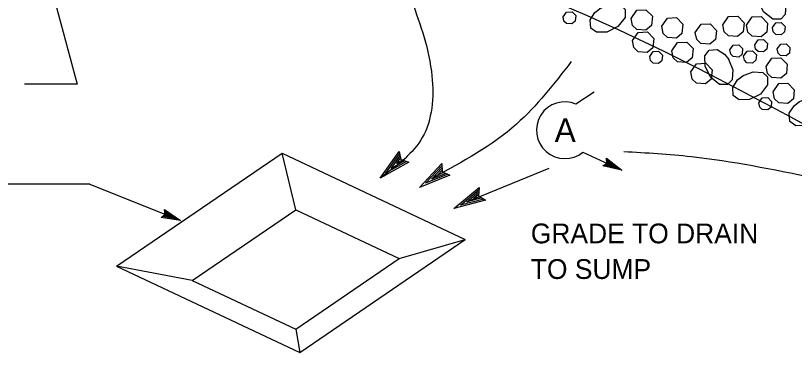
# Model space of a CAD drawing. Extents: x 6709491 to 6710959, y 1869789 to 1870763.
# Drawn here: x 6710515.2 to 6710751.9, y 1870221.6 to 1870323.8 of the extents above; entities that cross this region are included whole.
import ezdxf

# ---------------------------------------------------------------- set-up
doc = ezdxf.new("R2010")
doc.units = 0
for name, color, linetype in [('56 Stg 3 Anno', 7, 'Continuous'), ('57 Undefined', 7, 'Continuous'), ('60 Nongeo Data', 7, 'Continuous')]:
    doc.layers.add(name, color=color, linetype=linetype)

msp = doc.modelspace()

# ---------------------------------------------------------------- linework, layer by layer
at = {"layer": '56 Stg 3 Anno'}
for p, q in [((6710522.92, 1870344.3), (6710533.94, 1870302.96)), ((6710533.94, 1870302.96), (6710517.96, 1870302.96)), ((6710691.06, 1870300.55), (6710685.5, 1870296.97)), ((6710687.63, 1870282.38), (6710699.46, 1870276.93)), ((6710693.69, 1870278.18), (6710694.92, 1870279.02)), ((6710698.24, 1870277.49), (6710694.04, 1870278.4)), ((6710697.05, 1870278.04), (6710694.33, 1870278.63)), ((6710695.84, 1870278.6), (6710694.68, 1870278.85)), ((6710694.92, 1870279.02), (6710694.76, 1870280.51)), ((6710694.76, 1870280.51), (6710694.76, 1870280.51)), ((6710694.76, 1870280.51), (6710699.46, 1870276.93)), ((6710694.81, 1870280.11), (6710698.26, 1870277.49)), ((6710694.87, 1870279.71), (6710697.05, 1870278.04)), ((6710694.88, 1870279.33), (6710695.84, 1870278.6)), ((6710699.46, 1870276.93), (6710693.69, 1870278.18)), ((6710693.69, 1870278.18), (6710693.69, 1870278.18)), ((6710699.46, 1870276.93), (6710699.46, 1870276.93)), ((6710537.79, 1870272.64), (6710496.85, 1870272.64)), ((6710537.79, 1870272.64), (6710565.34, 1870261.62)), ((6710560.7, 1870263.47), (6710560.47, 1870264.95)), ((6710560.47, 1870264.95), (6710560.47, 1870264.95)), ((6710560.47, 1870264.95), (6710565.34, 1870261.62)), ((6710560.53, 1870264.56), (6710564.11, 1870262.11)), ((6710560.61, 1870264.15), (6710562.87, 1870262.6)), ((6710559.51, 1870262.57), (6710560.7, 1870263.47)), ((6710565.34, 1870261.62), (6710559.51, 1870262.57)), ((6710559.51, 1870262.57), (6710559.51, 1870262.57)), ((6710564.09, 1870262.11), (6710559.85, 1870262.81)), ((6710562.87, 1870262.6), (6710560.13, 1870263.05)), ((6710561.64, 1870263.1), (6710560.47, 1870263.29)), ((6710560.65, 1870263.78), (6710561.64, 1870263.1)), ((6710565.34, 1870261.62), (6710565.34, 1870261.62))]:
    msp.add_line(p, q, dxfattribs=at)
msp.add_arc((6710682.15, 1870289.04), 8.62, 67.1261, 309.4327, dxfattribs=at)
at = {"layer": '60 Nongeo Data'}
for p, q in [((6710545.91, 1870247.74), (6710596.21, 1870282.03)), ((6710596.21, 1870282.03), (6710651.87, 1870255.89)), ((6710600.37, 1870264.89), (6710596.21, 1870282.03)), ((6710626.02, 1870274.46), (6710631.78, 1870282.56)), ((6710627.69, 1870275.98), (6710631.89, 1870281.88)), ((6710629.34, 1870277.46), (6710632.05, 1870281.27)), ((6710631, 1870278.95), (6710632.16, 1870280.58)), ((6710631.78, 1870282.56), (6710631.78, 1870282.56)), ((6710631.78, 1870282.56), (6710632.26, 1870280.1)), ((6710634.68, 1870279.36), (6710626.02, 1870274.46)), ((6710634.03, 1870279.55), (6710627.68, 1870275.96)), ((6710633.36, 1870279.73), (6710629.34, 1870277.46)), ((6710632.77, 1870279.95), (6710631, 1870278.95)), ((6710632.26, 1870280.1), (6710634.68, 1870279.36)), ((6710634.68, 1870279.36), (6710634.68, 1870279.36)), ((6710637.96, 1870271.69), (6710644.74, 1870278.96)), ((6710639.81, 1870272.97), (6710644.76, 1870278.26)), ((6710644.74, 1870278.96), (6710644.74, 1870278.96)), ((6710644.74, 1870278.96), (6710644.89, 1870276.45)), ((6710641.64, 1870274.22), (6710644.84, 1870277.64)), ((6710645.93, 1870275.94), (6710641.64, 1870274.22)), ((6710643.49, 1870275.48), (6710644.85, 1870276.95)), ((6710645.38, 1870276.24), (6710643.49, 1870275.48)), ((6710644.89, 1870276.45), (6710647.18, 1870275.4)), ((6710677.28, 1870277.46), (6710652.25, 1870267.22)), ((6710626.02, 1870274.46), (6710626.02, 1870274.46)), ((6710647.18, 1870275.4), (6710637.96, 1870271.69)), ((6710646.57, 1870275.67), (6710639.8, 1870272.96)), ((6710647.18, 1870275.4), (6710647.18, 1870275.4)), ((6710637.96, 1870271.69), (6710637.96, 1870271.69)), ((6710648.41, 1870265.3), (6710656.08, 1870271.62)), ((6710656.08, 1870271.62), (6710655.91, 1870269.12)), ((6710656.08, 1870271.62), (6710656.08, 1870271.62)), ((6710650.42, 1870266.32), (6710656.01, 1870270.93)), ((6710652.4, 1870267.32), (6710656.01, 1870270.3)), ((6710654.39, 1870268.34), (6710655.93, 1870269.61)), ((6710656.36, 1870268.84), (6710654.39, 1870268.34)), ((6710655.91, 1870269.12), (6710658.04, 1870267.77)), ((6710658.04, 1870267.77), (6710648.41, 1870265.3)), ((6710657.47, 1870268.13), (6710650.4, 1870266.31)), ((6710656.87, 1870268.47), (6710652.4, 1870267.32)), ((6710658.04, 1870267.77), (6710658.04, 1870267.77)), ((6710568.89, 1870243.43), (6710600.37, 1870264.89)), ((6710600.37, 1870264.89), (6710631.82, 1870250.12)), ((6710648.41, 1870265.3), (6710648.41, 1870265.3)), ((6710601.56, 1870221.61), (6710651.87, 1870255.89)), ((6710631.82, 1870250.12), (6710651.87, 1870255.89)), ((6710600.34, 1870228.66), (6710631.82, 1870250.12)), ((6710545.91, 1870247.74), (6710601.56, 1870221.61)), ((6710568.89, 1870243.43), (6710545.91, 1870247.74)), ((6710568.89, 1870243.43), (6710600.34, 1870228.66)), ((6710600.34, 1870228.66), (6710601.56, 1870221.61))]:
    msp.add_line(p, q, dxfattribs=at)
for points in [[(6710748.03, 1870330.39), (6710749.32, 1870327.14), (6710749.06, 1870324.15), (6710747.71, 1870322.73), (6710745.28, 1870322.77), (6710742.53, 1870324.93), (6710740.86, 1870328.26), (6710740.81, 1870331.4), (6710742.06, 1870333.17), (6710744.56, 1870333.34), (6710746.8, 1870331.9), (6710748.11, 1870330.26)], [(6710692.79, 1870325.96), (6710696.05, 1870327.25), (6710699.03, 1870327), (6710700.46, 1870325.64), (6710700.41, 1870323.22), (6710698.25, 1870320.46), (6710694.92, 1870318.8), (6710691.78, 1870318.74), (6710690.01, 1870320), (6710689.85, 1870322.5), (6710691.28, 1870324.74), (6710692.92, 1870326.05)], [(6710702.26, 1870322.96), (6710704, 1870325.43), (6710706.77, 1870325.59), (6710708.71, 1870323.59), (6710708.43, 1870320.78), (6710706.71, 1870319.36), (6710703.97, 1870319.56), (6710702.68, 1870320.81), (6710702.26, 1870322.96)], [(6710681.59, 1870323.42), (6710682.63, 1870324.9), (6710684.3, 1870325), (6710685.46, 1870323.8), (6710685.29, 1870322.11), (6710684.26, 1870321.26), (6710682.61, 1870321.38), (6710681.84, 1870322.13), (6710681.59, 1870323.42)], [(6710711.56, 1870320.56), (6710713.29, 1870323.03), (6710716.07, 1870323.19), (6710718, 1870321.19), (6710717.72, 1870318.39), (6710716.01, 1870316.96), (6710713.27, 1870317.16), (6710711.98, 1870318.41), (6710711.56, 1870320.56)], [(6710730.12, 1870321.02), (6710731.86, 1870323.5), (6710734.64, 1870323.66), (6710736.57, 1870321.65), (6710736.29, 1870318.85), (6710734.57, 1870317.42), (6710731.83, 1870317.62), (6710730.54, 1870318.87), (6710730.12, 1870321.02)], [(6710737.28, 1870320.92), (6710739.02, 1870323.39), (6710741.79, 1870323.55), (6710743.73, 1870321.55), (6710743.45, 1870318.74), (6710741.73, 1870317.32), (6710738.99, 1870317.52), (6710737.7, 1870318.77), (6710737.28, 1870320.92)], [(6710721.77, 1870318.7), (6710723.51, 1870321.18), (6710726.28, 1870321.33), (6710728.21, 1870319.33), (6710727.93, 1870316.53), (6710726.22, 1870315.1), (6710723.48, 1870315.3), (6710722.19, 1870316.55), (6710721.77, 1870318.7)], [(6710745.19, 1870320.15), (6710746.24, 1870321.64), (6710747.9, 1870321.73), (6710749.06, 1870320.53), (6710748.89, 1870318.85), (6710747.86, 1870317.99), (6710746.22, 1870318.11), (6710745.44, 1870318.86), (6710745.19, 1870320.15)], [(6710702.69, 1870316.24), (6710704.43, 1870318.71), (6710707.21, 1870318.87), (6710709.14, 1870316.87), (6710708.86, 1870314.06), (6710707.15, 1870312.64), (6710704.41, 1870312.84), (6710703.11, 1870314.09), (6710702.7, 1870316.24)], [(6710739.81, 1870314.93), (6710740.85, 1870316.42), (6710742.52, 1870316.51), (6710743.68, 1870315.31), (6710743.51, 1870313.63), (6710742.48, 1870312.77), (6710740.83, 1870312.89), (6710740.06, 1870313.64), (6710739.81, 1870314.93)], [(6710714.65, 1870313.15), (6710716.39, 1870315.63), (6710719.16, 1870315.78), (6710721.09, 1870313.78), (6710720.82, 1870310.98), (6710719.1, 1870309.55), (6710716.36, 1870309.75), (6710715.07, 1870311), (6710714.65, 1870313.15)], [(6710732.27, 1870313.4), (6710733.31, 1870314.88), (6710734.98, 1870314.98), (6710736.14, 1870313.78), (6710735.97, 1870312.1), (6710734.94, 1870311.24), (6710733.3, 1870311.36), (6710732.52, 1870312.11), (6710732.27, 1870313.4)], [(6710746.66, 1870313.71), (6710747.7, 1870315.19), (6710749.37, 1870315.29), (6710750.53, 1870314.09), (6710750.36, 1870312.41), (6710749.33, 1870311.55), (6710747.69, 1870311.67), (6710746.91, 1870312.42), (6710746.66, 1870313.71)], [(6710707.92, 1870311.44), (6710708.97, 1870312.92), (6710710.63, 1870313.02), (6710711.79, 1870311.82), (6710711.63, 1870310.13), (6710710.6, 1870309.28), (6710708.95, 1870309.4), (6710708.18, 1870310.15), (6710707.93, 1870311.44)], [(6710731.89, 1870310.57), (6710733.18, 1870307.31), (6710732.92, 1870304.32), (6710731.57, 1870302.9), (6710729.15, 1870302.95), (6710726.39, 1870305.1), (6710724.73, 1870308.44), (6710724.67, 1870311.58), (6710725.93, 1870313.35), (6710728.43, 1870313.51), (6710730.66, 1870312.08), (6710731.98, 1870310.44)], [(6710736.45, 1870311.54), (6710737.49, 1870313.03), (6710739.16, 1870313.12), (6710740.32, 1870311.92), (6710740.15, 1870310.24), (6710739.12, 1870309.38), (6710737.47, 1870309.5), (6710736.7, 1870310.25), (6710736.45, 1870311.54)], [(6710720.4, 1870306.7), (6710722.14, 1870309.17), (6710724.92, 1870309.33), (6710726.85, 1870307.33), (6710726.57, 1870304.53), (6710724.85, 1870303.1), (6710722.11, 1870303.3), (6710720.82, 1870304.55), (6710720.4, 1870306.7)], [(6710743.26, 1870308.41), (6710745, 1870310.88), (6710747.78, 1870311.04), (6710749.71, 1870309.04), (6710749.43, 1870306.23), (6710747.71, 1870304.81), (6710744.97, 1870305.01), (6710743.68, 1870306.26), (6710743.26, 1870308.41)], [(6710736.07, 1870305.49), (6710739.32, 1870306.78), (6710742.31, 1870306.53), (6710743.73, 1870305.18), (6710743.69, 1870302.75), (6710741.53, 1870299.99), (6710738.2, 1870298.33), (6710735.06, 1870298.27), (6710733.29, 1870299.53), (6710733.13, 1870302.03), (6710734.56, 1870304.27), (6710736.2, 1870305.58)], [(6710745.4, 1870300.7), (6710747.14, 1870303.17), (6710749.92, 1870303.33), (6710751.85, 1870301.33), (6710751.57, 1870298.52), (6710749.85, 1870297.1), (6710747.11, 1870297.3), (6710745.82, 1870298.55), (6710745.4, 1870300.7)], [(6710741.08, 1870297.34), (6710742.12, 1870298.83), (6710743.79, 1870298.92), (6710744.94, 1870297.72), (6710744.78, 1870296.04), (6710743.75, 1870295.18), (6710742.1, 1870295.3), (6710741.33, 1870296.05), (6710741.08, 1870297.34)], [(6710753.27, 1870297.62), (6710756.53, 1870298.91), (6710759.51, 1870298.65), (6710760.94, 1870297.3), (6710760.89, 1870294.88), (6710758.73, 1870292.12), (6710755.4, 1870290.46), (6710752.26, 1870290.4), (6710750.49, 1870291.66), (6710750.33, 1870294.16), (6710751.76, 1870296.4), (6710753.4, 1870297.71)]]:
    msp.add_lwpolyline(points, dxfattribs=at)
for points in [[(6710505.99, 1870337.51), (6710532.99, 1870347.83), (6710590.83, 1870352.57), (6710625.79, 1870346.13), (6710776.97, 1870278.77)], [(6710635.61, 1870328.27), (6710641.74, 1870305.49), (6710638.82, 1870286.79), (6710626.85, 1870275.11)], [(6710684.07, 1870309.87), (6710667.43, 1870290.88), (6710642.03, 1870274.53)], [(6710757.64, 1870274.53), (6710720.56, 1870280.95), (6710700.05, 1870282.48)]]:
    msp.add_spline(points, degree=3, dxfattribs=at)

# ---------------------------------------------------------------- texts
at = {"layer": '57 Undefined'}
for s, height, p in [('A', 7.21, (6710679.02, 1870285.43)), ('GRADE TO DRAIN ', 6, (6710671.79, 1870254.7)), ('TO SUMP', 6, (6710671.79, 1870243.9))]:
    msp.add_text(s, height=height, dxfattribs=at).set_placement(p)

doc.saveas('drawing.dxf')
